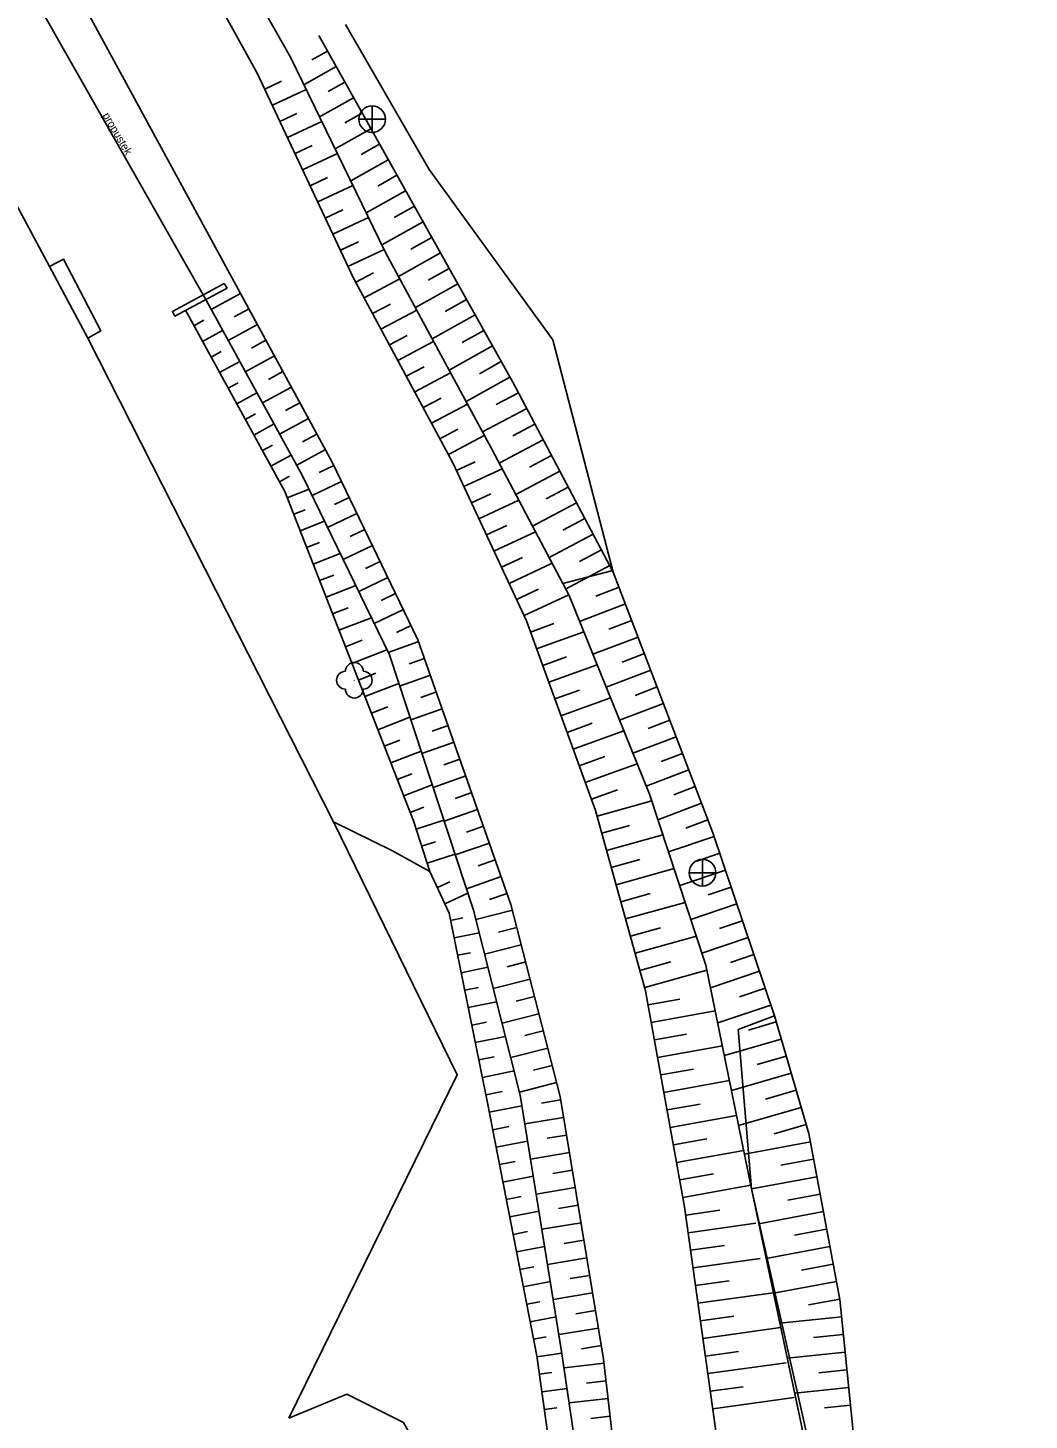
# Model space of a CAD drawing. Extents: x -747135 to -746147, y -1093269 to -1091735.
# Drawn here: x -746689.1 to -746632.7, y -1092579.8 to -1092501.6 of the extents above; entities that cross this region are included whole.
import ezdxf

# ---------------------------------------------------------------- set-up
doc = ezdxf.new("R2010")
doc.units = 0
for name, color, linetype in [('101', 7, 'Continuous'), ('1016', 7, 'Continuous'), ('105', 7, 'Continuous'), ('23700', 7, 'Continuous'), ('308', 7, 'Continuous'), ('316', 7, 'Continuous'), ('424', 7, 'Continuous'), ('803', 7, 'Continuous')]:
    doc.layers.add(name, color=color, linetype=linetype)

msp = doc.modelspace()

# ---------------------------------------------------------------- linework, layer by layer
at = {"layer": '101'}
for points in [[(-746672.69, -1092502.01), (-746661.78, -1092521.49), (-746656.13, -1092532.17)], [(-746674.28, -1092503.22), (-746668.93, -1092514.2), (-746662.98, -1092525.23), (-746658.61, -1092533.49), (-746654.09, -1092544.66), (-746650.92, -1092554.26), (-746648.35, -1092566.85), (-746644.79, -1092583.69), (-746644.13, -1092588.78), (-746644.17, -1092602.45), (-746642.4, -1092621.5)], [(-746672.201, -1092502.882), (-746673.082, -1092503.376)], [(-746671.713, -1092503.755), (-746673.525, -1092504.77)], [(-746675.725, -1092505.025), (-746674.779, -1092504.581)], [(-746671.224, -1092504.627), (-746672.155, -1092505.149)], [(-746675.3, -1092505.93), (-746673.395, -1092505.036)], [(-746670.735, -1092505.5), (-746672.647, -1092506.571)], [(-746674.875, -1092506.835), (-746673.916, -1092506.385)], [(-746670.247, -1092506.372), (-746671.228, -1092506.922)], [(-746674.45, -1092507.741), (-746672.519, -1092506.834)], [(-746669.758, -1092507.245), (-746671.77, -1092508.372)], [(-746674.025, -1092508.646), (-746673.053, -1092508.189)], [(-746673.6, -1092509.551), (-746671.643, -1092508.632)], [(-746669.269, -1092508.117), (-746670.3, -1092508.695)], [(-746668.781, -1092508.99), (-746670.892, -1092510.172)], [(-746673.174, -1092510.456), (-746672.19, -1092509.994)], [(-746668.292, -1092509.862), (-746669.373, -1092510.468)], [(-746672.749, -1092511.361), (-746670.767, -1092510.43)], [(-746667.804, -1092510.735), (-746670.015, -1092511.973)], [(-746672.324, -1092512.266), (-746671.327, -1092511.798)], [(-746667.315, -1092511.607), (-746668.446, -1092512.241)], [(-746671.899, -1092513.172), (-746669.891, -1092512.228)], [(-746666.826, -1092512.48), (-746669.137, -1092513.774)], [(-746666.338, -1092513.352), (-746667.509, -1092514.008)], [(-746671.474, -1092514.077), (-746670.463, -1092513.602)], [(-746671.049, -1092514.982), (-746669.015, -1092514.026)], [(-746665.849, -1092514.225), (-746668.205, -1092515.544)], [(-746665.36, -1092515.097), (-746666.545, -1092515.761)], [(-746670.611, -1092515.88), (-746669.608, -1092515.341)], [(-746670.137, -1092516.761), (-746668.131, -1092515.682)], [(-746677.089, -1092516.501), (-746678.748, -1092517.402)], [(-746664.872, -1092515.97), (-746667.255, -1092517.305)], [(-746643.03, -1092728.31), (-746645.35, -1092706.55), (-746647.64, -1092685.53), (-746650.22, -1092662.21), (-746652.01, -1092645.97), (-746654.41, -1092623.21), (-746657.16, -1092600.72), (-746657.52, -1092586.28), (-746659.03, -1092575.98), (-746661.36, -1092561.58), (-746663.99, -1092551.17), (-746668.72, -1092536.82), (-746673.6, -1092526.76), (-746679.03, -1092516.89)], [(-746676.612, -1092517.38), (-746677.439, -1092517.829)], [(-746669.663, -1092517.642), (-746668.66, -1092517.102)], [(-746669.19, -1092518.522), (-746667.181, -1092517.442)], [(-746664.383, -1092516.842), (-746665.582, -1092517.514)], [(-746680.19, -1092517.45), (-746674.6, -1092527.64), (-746667.37, -1092546.15), (-746666.44, -1092549)], [(-746679.709, -1092518.327), (-746679.145, -1092518.017)], [(-746663.894, -1092517.715), (-746666.306, -1092519.065)], [(-746679.228, -1092519.203), (-746678.098, -1092518.584)], [(-746676.135, -1092518.259), (-746677.784, -1092519.154)], [(-746668.716, -1092519.403), (-746667.711, -1092518.863)], [(-746663.406, -1092518.587), (-746664.618, -1092519.266)], [(-746678.747, -1092520.08), (-746678.182, -1092519.77)], [(-746675.658, -1092519.137), (-746676.48, -1092519.584)], [(-746668.242, -1092520.284), (-746666.232, -1092519.202)], [(-746662.917, -1092519.46), (-746665.356, -1092520.826)], [(-746678.266, -1092520.957), (-746677.134, -1092520.336)], [(-746675.18, -1092520.016), (-746676.82, -1092520.907)], [(-746662.428, -1092520.332), (-746663.655, -1092521.019)], [(-746674.703, -1092520.895), (-746675.521, -1092521.339)], [(-746667.769, -1092521.164), (-746666.763, -1092520.623)], [(-746667.295, -1092522.045), (-746665.282, -1092520.963)], [(-746661.94, -1092521.205), (-746664.406, -1092522.586)], [(-746677.785, -1092521.834), (-746677.219, -1092521.523)], [(-746677.304, -1092522.71), (-746676.17, -1092522.088)], [(-746674.226, -1092521.774), (-746675.856, -1092522.659)], [(-746661.465, -1092522.085), (-746662.714, -1092522.746)], [(-746673.748, -1092522.652), (-746674.561, -1092523.094)], [(-746666.821, -1092522.926), (-746665.814, -1092522.384)], [(-746666.347, -1092523.807), (-746664.332, -1092522.723)], [(-746676.823, -1092523.587), (-746676.256, -1092523.276)], [(-746673.271, -1092523.531), (-746674.892, -1092524.411)], [(-746660.998, -1092522.969), (-746663.489, -1092524.287)], [(-746676.342, -1092524.464), (-746675.206, -1092523.841)], [(-746672.794, -1092524.41), (-746673.602, -1092524.849)], [(-746665.874, -1092524.687), (-746664.866, -1092524.145)], [(-746665.4, -1092525.568), (-746663.383, -1092524.483)], [(-746660.53, -1092523.853), (-746661.772, -1092524.51)], [(-746675.861, -1092525.341), (-746675.293, -1092525.029)], [(-746660.062, -1092524.737), (-746662.546, -1092526.05)], [(-746675.38, -1092526.217), (-746674.242, -1092525.593)], [(-746672.316, -1092525.288), (-746673.928, -1092526.164)], [(-746664.948, -1092526.46), (-746663.898, -1092525.97)], [(-746659.595, -1092525.621), (-746660.837, -1092526.277)], [(-746674.899, -1092527.094), (-746674.33, -1092526.782)], [(-746671.847, -1092526.171), (-746672.673, -1092526.57)], [(-746664.526, -1092527.366), (-746662.379, -1092526.366)], [(-746659.127, -1092526.504), (-746661.611, -1092527.818)], [(-746674.463, -1092527.992), (-746673.235, -1092527.512)], [(-746671.412, -1092527.072), (-746673.062, -1092527.869)], [(-746658.66, -1092527.388), (-746659.901, -1092528.045)], [(-746670.977, -1092527.972), (-746671.801, -1092528.37)], [(-746664.104, -1092528.272), (-746663.007, -1092527.762)], [(-746663.681, -1092529.179), (-746661.443, -1092528.136)], [(-746658.192, -1092528.272), (-746660.675, -1092529.586)], [(-746674.099, -1092528.923), (-746673.448, -1092528.669)], [(-746670.541, -1092528.872), (-746672.189, -1092529.669)], [(-746657.724, -1092529.156), (-746658.966, -1092529.813)], [(-746673.735, -1092529.854), (-746672.36, -1092529.317)], [(-746670.106, -1092529.773), (-746670.929, -1092530.171)], [(-746663.259, -1092530.085), (-746662.117, -1092529.553)], [(-746662.836, -1092530.992), (-746660.506, -1092529.906)], [(-746673.371, -1092530.786), (-746672.646, -1092530.503)], [(-746669.671, -1092530.673), (-746671.316, -1092531.468)], [(-746657.257, -1092530.04), (-746659.74, -1092531.354)], [(-746673.007, -1092531.717), (-746671.484, -1092531.122)], [(-746662.414, -1092531.898), (-746661.226, -1092531.344)], [(-746656.789, -1092530.924), (-746658.031, -1092531.581)], [(-746669.236, -1092531.573), (-746670.058, -1092531.971)], [(-746661.991, -1092532.804), (-746659.57, -1092531.676)], [(-746656.153, -1092532.083), (-746658.966, -1092532.816)], [(-746656.321, -1092531.808), (-746658.805, -1092533.122)], [(-746672.644, -1092532.649), (-746671.845, -1092532.337)], [(-746672.28, -1092533.58), (-746670.608, -1092532.927)], [(-746668.8, -1092532.473), (-746670.443, -1092533.268)], [(-746655.805, -1092533.02), (-746657.102, -1092533.517)], [(-746668.365, -1092533.374), (-746669.186, -1092533.771)], [(-746661.569, -1092533.711), (-746660.335, -1092533.136)], [(-746661.146, -1092534.617), (-746658.633, -1092533.446)], [(-746671.916, -1092534.512), (-746671.043, -1092534.171)], [(-746667.93, -1092534.274), (-746669.57, -1092535.067)], [(-746655.447, -1092533.954), (-746658.023, -1092534.94)], [(-746671.552, -1092535.443), (-746669.733, -1092534.733)], [(-746667.495, -1092535.174), (-746668.314, -1092535.571)], [(-746660.778, -1092535.546), (-746659.471, -1092535.07)], [(-746655.09, -1092534.888), (-746656.369, -1092535.378)], [(-746671.188, -1092536.375), (-746670.241, -1092536.005)], [(-746667.071, -1092536.08), (-746668.787, -1092536.682)], [(-746660.436, -1092536.486), (-746657.788, -1092535.522)], [(-746654.732, -1092535.822), (-746657.273, -1092536.794)], [(-746670.824, -1092537.306), (-746668.857, -1092536.538)], [(-746660.094, -1092537.426), (-746658.753, -1092536.937)], [(-746654.375, -1092536.756), (-746655.636, -1092537.239)], [(-746666.74, -1092537.023), (-746667.597, -1092537.324)], [(-746659.752, -1092538.365), (-746657.037, -1092537.377)], [(-746654.018, -1092537.69), (-746656.523, -1092538.649)], [(-746670.461, -1092538.238), (-746669.483, -1092537.856)], [(-746670.097, -1092539.169), (-746668.191, -1092538.425)], [(-746666.409, -1092537.967), (-746668.141, -1092538.575)], [(-746666.077, -1092538.91), (-746666.953, -1092539.218)], [(-746659.41, -1092539.305), (-746658.036, -1092538.805)], [(-746659.068, -1092540.245), (-746656.286, -1092539.232)], [(-746653.66, -1092538.624), (-746654.904, -1092539.1)], [(-746669.733, -1092540.101), (-746668.805, -1092539.738)], [(-746665.746, -1092539.854), (-746667.515, -1092540.475)], [(-746653.303, -1092539.558), (-746655.772, -1092540.503)], [(-746669.369, -1092541.032), (-746667.564, -1092540.327)], [(-746665.414, -1092540.797), (-746666.308, -1092541.111)], [(-746658.726, -1092541.184), (-746657.319, -1092540.672)], [(-746652.945, -1092540.492), (-746654.171, -1092540.961)], [(-746669.005, -1092541.964), (-746668.128, -1092541.621)], [(-746658.384, -1092542.124), (-746655.536, -1092541.087)], [(-746652.588, -1092541.426), (-746655.022, -1092542.357)], [(-746668.641, -1092542.895), (-746666.937, -1092542.229)], [(-746665.083, -1092541.741), (-746666.889, -1092542.375)], [(-746652.231, -1092542.36), (-746653.439, -1092542.822)], [(-746664.752, -1092542.684), (-746665.664, -1092543.005)], [(-746658.042, -1092543.064), (-746656.601, -1092542.539)], [(-746657.7, -1092544.003), (-746654.785, -1092542.942)], [(-746668.278, -1092543.826), (-746667.451, -1092543.503)], [(-746664.42, -1092543.628), (-746666.263, -1092544.275)], [(-746651.873, -1092543.294), (-746654.271, -1092544.211)], [(-746667.914, -1092544.758), (-746666.31, -1092544.132)], [(-746664.089, -1092544.571), (-746665.019, -1092544.898)], [(-746657.358, -1092544.943), (-746655.884, -1092544.406)], [(-746651.516, -1092544.228), (-746652.722, -1092544.689)], [(-746667.55, -1092545.689), (-746666.773, -1092545.386)], [(-746663.758, -1092545.515), (-746665.637, -1092546.175)], [(-746657.041, -1092545.891), (-746653.966, -1092545.036)], [(-746651.158, -1092545.162), (-746653.614, -1092546.101)], [(-746667.213, -1092546.631), (-746665.654, -1092546.122)], [(-746650.801, -1092546.096), (-746652.051, -1092546.574)], [(-746663.426, -1092546.458), (-746664.375, -1092546.791)], [(-746656.773, -1092546.854), (-746655.212, -1092546.42)], [(-746656.505, -1092547.818), (-746653.338, -1092546.937)], [(-746650.452, -1092547.033), (-746653.021, -1092547.896)], [(-746666.903, -1092547.581), (-746666.122, -1092547.326)], [(-746663.095, -1092547.402), (-746665.01, -1092548.074)], [(-746666.593, -1092548.532), (-746665.028, -1092548.021)], [(-746662.763, -1092548.345), (-746663.73, -1092548.685)], [(-746656.237, -1092548.781), (-746654.631, -1092548.334)], [(-746650.133, -1092547.98), (-746651.42, -1092548.413)], [(-746662.432, -1092549.289), (-746664.384, -1092549.974)], [(-746655.969, -1092549.744), (-746652.71, -1092548.838)], [(-746649.814, -1092548.928), (-746652.394, -1092549.796)], [(-746666.021, -1092549.908), (-746665.32, -1092549.584)], [(-746665.602, -1092550.816), (-746664.304, -1092550.217)], [(-746662.101, -1092550.232), (-746663.086, -1092550.578)], [(-746655.701, -1092550.708), (-746654.049, -1092550.248)], [(-746649.496, -1092549.876), (-746650.788, -1092550.311)], [(-746655.433, -1092551.671), (-746652.083, -1092550.739)], [(-746649.177, -1092550.824), (-746651.767, -1092551.695)], [(-746665.276, -1092551.754), (-746664.594, -1092551.616)], [(-746661.797, -1092551.184), (-746663.854, -1092551.71)], [(-746648.858, -1092551.772), (-746650.156, -1092552.208)], [(-746665.078, -1092552.735), (-746663.667, -1092552.449)], [(-746661.549, -1092552.153), (-746662.579, -1092552.416)], [(-746655.165, -1092552.635), (-746653.467, -1092552.162)], [(-746654.897, -1092553.598), (-746651.455, -1092552.641)], [(-746661.301, -1092553.122), (-746663.364, -1092553.649)], [(-746648.54, -1092552.72), (-746651.14, -1092553.594)], [(-746664.879, -1092553.715), (-746664.15, -1092553.567)], [(-746661.054, -1092554.09), (-746662.086, -1092554.355)], [(-746654.629, -1092554.562), (-746652.885, -1092554.076)], [(-746648.221, -1092553.667), (-746649.54, -1092554.111)], [(-746664.681, -1092554.695), (-746663.176, -1092554.39)], [(-746654.361, -1092555.525), (-746650.861, -1092554.551)], [(-746647.902, -1092554.615), (-746650.658, -1092555.542)], [(-746664.482, -1092555.675), (-746663.707, -1092555.518)], [(-746660.806, -1092555.059), (-746662.874, -1092555.588)], [(-746647.583, -1092555.563), (-746649.02, -1092556.046)], [(-746664.284, -1092556.655), (-746662.686, -1092556.331)], [(-746660.558, -1092556.028), (-746661.593, -1092556.293)], [(-746654.167, -1092556.505), (-746652.38, -1092556.183)], [(-746647.265, -1092556.511), (-746650.255, -1092557.517)], [(-746660.31, -1092556.997), (-746662.384, -1092557.527)], [(-746653.989, -1092557.489), (-746650.393, -1092556.841)], [(-746664.086, -1092557.635), (-746663.263, -1092557.469)], [(-746660.062, -1092557.966), (-746661.101, -1092558.231)], [(-746653.812, -1092558.473), (-746652.002, -1092558.147)], [(-746646.96, -1092557.463), (-746648.52, -1092557.918)], [(-746663.887, -1092558.615), (-746662.196, -1092558.273)], [(-746653.634, -1092559.457), (-746649.993, -1092558.801)], [(-746646.68, -1092558.423), (-746649.88, -1092559.356)], [(-746663.689, -1092559.595), (-746662.82, -1092559.419)], [(-746659.815, -1092558.935), (-746661.894, -1092559.466)], [(-746646.4, -1092559.383), (-746648.04, -1092559.861)], [(-746663.49, -1092560.575), (-746661.705, -1092560.214)], [(-746659.567, -1092559.903), (-746660.608, -1092560.17)], [(-746653.456, -1092560.442), (-746651.625, -1092560.111)], [(-746646.12, -1092560.343), (-746649.478, -1092561.322)], [(-746659.319, -1092560.872), (-746661.404, -1092561.406)], [(-746653.279, -1092561.426), (-746649.593, -1092560.761)], [(-746663.292, -1092561.556), (-746662.376, -1092561.37)], [(-746659.088, -1092561.844), (-746660.173, -1092562.025)], [(-746645.84, -1092561.303), (-746647.559, -1092561.804)], [(-746663.098, -1092562.536), (-746661.263, -1092562.179)], [(-746658.924, -1092562.831), (-746661.099, -1092563.192)], [(-746653.101, -1092562.41), (-746651.247, -1092562.075)], [(-746652.924, -1092563.394), (-746649.193, -1092562.721)], [(-746645.56, -1092562.263), (-746649.077, -1092563.289)], [(-746662.906, -1092563.518), (-746662.005, -1092563.343)], [(-746645.281, -1092563.223), (-746647.078, -1092563.748)], [(-746662.715, -1092564.5), (-746660.943, -1092564.155)], [(-746658.76, -1092563.817), (-746659.85, -1092563.998)], [(-746652.746, -1092564.378), (-746650.87, -1092564.04)], [(-746645.045, -1092564.194), (-746648.751, -1092564.885)], [(-746658.597, -1092564.804), (-746660.78, -1092565.166)], [(-746652.569, -1092565.362), (-746648.793, -1092564.681)], [(-746644.862, -1092565.177), (-746646.707, -1092565.521)], [(-746662.524, -1092565.481), (-746661.654, -1092565.312)], [(-746658.433, -1092565.791), (-746659.527, -1092565.972)], [(-746662.333, -1092566.463), (-746660.624, -1092566.13)], [(-746652.391, -1092566.346), (-746650.492, -1092566.004)], [(-746652.214, -1092567.33), (-746648.393, -1092566.641)], [(-746644.679, -1092566.16), (-746648.351, -1092566.845)], [(-746662.142, -1092567.444), (-746661.303, -1092567.281)], [(-746658.27, -1092566.777), (-746660.46, -1092567.14)], [(-746644.495, -1092567.143), (-746646.32, -1092567.483)], [(-746661.951, -1092568.426), (-746660.304, -1092568.105)], [(-746658.106, -1092567.764), (-746659.203, -1092567.946)], [(-746652.055, -1092568.317), (-746650.144, -1092568.051)], [(-746644.312, -1092568.126), (-746647.937, -1092568.802)], [(-746657.942, -1092568.75), (-746660.141, -1092569.115)], [(-746651.917, -1092569.308), (-746648.109, -1092568.776)], [(-746661.76, -1092569.408), (-746660.952, -1092569.25)], [(-746657.779, -1092569.737), (-746658.88, -1092569.919)], [(-746644.129, -1092569.109), (-746645.93, -1092569.445)], [(-746661.569, -1092570.389), (-746659.985, -1092570.081)], [(-746651.778, -1092570.298), (-746649.881, -1092570.034)], [(-746643.945, -1092570.092), (-746647.523, -1092570.76)], [(-746661.378, -1092571.371), (-746660.601, -1092571.219)], [(-746657.615, -1092570.723), (-746659.821, -1092571.089)], [(-746651.64, -1092571.289), (-746647.86, -1092570.761)], [(-746643.762, -1092571.075), (-746645.539, -1092571.407)], [(-746661.187, -1092572.352), (-746659.665, -1092572.056)], [(-746657.451, -1092571.71), (-746658.556, -1092571.893)], [(-746651.502, -1092572.279), (-746649.619, -1092572.016)], [(-746643.579, -1092572.058), (-746647.11, -1092572.717)], [(-746657.288, -1092572.696), (-746659.502, -1092573.063)], [(-746651.364, -1092573.27), (-746647.144, -1092572.681)], [(-746660.996, -1092573.334), (-746660.25, -1092573.189)], [(-746657.124, -1092573.683), (-746658.233, -1092573.867)], [(-746643.395, -1092573.042), (-746645.149, -1092573.369)], [(-746660.805, -1092574.315), (-746659.345, -1092574.031)], [(-746651.225, -1092574.26), (-746649.356, -1092573.999)], [(-746643.292, -1092574.036), (-746646.757, -1092574.386)], [(-746660.614, -1092575.297), (-746659.9, -1092575.158)], [(-746656.96, -1092574.669), (-746659.182, -1092575.038)], [(-746651.087, -1092575.25), (-746646.716, -1092574.64)], [(-746643.192, -1092575.031), (-746644.87, -1092575.201)], [(-746660.425, -1092576.279), (-746659.015, -1092576.081)], [(-746656.797, -1092575.656), (-746657.91, -1092575.84)], [(-746650.949, -1092576.241), (-746649.094, -1092575.982)], [(-746643.091, -1092576.026), (-746646.341, -1092576.354)], [(-746656.645, -1092576.644), (-746658.895, -1092576.9)], [(-746650.811, -1092577.231), (-746646.401, -1092576.616)], [(-746660.286, -1092577.269), (-746659.578, -1092577.17)], [(-746656.531, -1092577.637), (-746657.641, -1092577.764)], [(-746642.991, -1092577.021), (-746644.562, -1092577.18)], [(-746660.147, -1092578.26), (-746658.725, -1092578.06)], [(-746650.673, -1092578.222), (-746648.831, -1092577.965)], [(-746642.89, -1092578.016), (-746645.925, -1092578.323)], [(-746660.008, -1092579.25), (-746659.294, -1092579.15)], [(-746656.418, -1092578.631), (-746658.605, -1092578.88)], [(-746650.534, -1092579.212), (-746645.951, -1092578.572)], [(-746642.79, -1092579.011), (-746644.253, -1092579.159)], [(-746656.305, -1092579.625), (-746657.382, -1092579.747)]]:
    msp.add_lwpolyline(points, dxfattribs=at)
at = {"layer": '1016'}
for points in [[(-746680.08, -1092497.02), (-746676.15, -1092504.12)], [(-746677.329, -1092516.059), (-746686.53, -1092499.12)], [(-746676.15, -1092504.12), (-746670.74, -1092515.64), (-746665.13, -1092526.07), (-746661.01, -1092534.91), (-746657.13, -1092545.57), (-746654.31, -1092555.71), (-746652.12, -1092567.85), (-746649.95, -1092583.4), (-746648.25, -1092600.5), (-746646.08, -1092622.58)], [(-746677.85, -1092516.21), (-746680.78, -1092517.78), (-746680.922, -1092517.516), (-746678.018, -1092515.949), (-746677.85, -1092516.21)], [(-746640.293, -1092727.76), (-746642.73, -1092706.84), (-746645.07, -1092684.23), (-746647.45, -1092662.17), (-746649.23, -1092645.87), (-746651.64, -1092623.4), (-746654, -1092600.5), (-746655.65, -1092585.38), (-746656.67, -1092576.42), (-746659.12, -1092561.65), (-746661.88, -1092550.86), (-746667.11, -1092535.97), (-746671.93, -1092526), (-746677.329, -1092516.06)]]:
    msp.add_lwpolyline(points, dxfattribs=at)
at = {"layer": '23700'}
for points in [[(-746678.42, -1092495.91), (-746674.28, -1092503.22)], [(-746688.39, -1092500.4), (-746679.03, -1092516.89)]]:
    msp.add_lwpolyline(points, dxfattribs=at)
at = {"layer": '308'}
msp.add_lwpolyline([(-746685.68, -1092519.02), (-746689.71, -1092511.48)], dxfattribs=at)
at = {"layer": '316'}
for p, q in [((-746669.691, -1092507.458), (-746669.69, -1092505.963)), ((-746668.938, -1092506.716), (-746670.438, -1092506.711)), ((-746651.111, -1092549.818), (-746651.11, -1092548.323)), ((-746650.358, -1092549.076), (-746651.858, -1092549.071))]:
    msp.add_line(p, q, dxfattribs=at)
for centre in [(-746669.69, -1092506.71), (-746651.11, -1092549.07)]:
    msp.add_circle(centre, 0.75, dxfattribs=at)
at = {"layer": '424'}
for points in [[(-746632.74, -1092626.58), (-746635.64, -1092620.77), (-746637.67, -1092615.33), (-746638.38, -1092607.28), (-746642.34, -1092583.46), (-746643.39, -1092573.07), (-746645.13, -1092563.74), (-746647.06, -1092557.12), (-746650.52, -1092546.83), (-746656.13, -1092532.17), (-746659.53, -1092519.12), (-746666.48, -1092509.53), (-746671.18, -1092501.38)], [(-746671.86, -1092546.22), (-746668.58, -1092547.82), (-746666.44, -1092549)], [(-746666.44, -1092549), (-746665.36, -1092551.34), (-746663.2, -1092562.01), (-746660.43, -1092576.24), (-746658.93, -1092586.95), (-746657.16, -1092600.72), (-746656.07, -1092616.52), (-746651.4, -1092662.02)], [(-746647.06, -1092557.12), (-746649.1, -1092557.89), (-746648.35, -1092566.85), (-746644.58, -1092583.56), (-746643.94, -1092588.6), (-746643.94, -1092602.65), (-746640.7, -1092621.81)], [(-746674.37, -1092579.73), (-746671.11, -1092578.39), (-746667.92, -1092579.98), (-746662.95, -1092588.94), (-746660.74, -1092596.69), (-746659.38, -1092604.06), (-746657.87, -1092616.28)]]:
    msp.add_lwpolyline(points, dxfattribs=at)
msp.add_circle((-746670.69, -1092538.25), 0.0005, dxfattribs=at)
for centre, start, end in [((-746671.19, -1092538.25), 89.99999, 269.99999), ((-746670.69, -1092537.75), 0, 179.99999), ((-746670.19, -1092538.25), 270, 89.99999), ((-746670.69, -1092538.75), 179.99999, 359.99999)]:
    msp.add_arc(centre, 0.5, start, end, dxfattribs=at)
at = {"layer": '803'}
for points in [[(-746685.68, -1092519.02), (-746684.95, -1092518.61), (-746687.04, -1092514.58), (-746687.83, -1092514.99)], [(-746674.37, -1092579.73), (-746664.9, -1092560.44), (-746671.86, -1092546.22), (-746685.68, -1092519.02)]]:
    msp.add_lwpolyline(points, dxfattribs=at)

# ---------------------------------------------------------------- texts
at = {"layer": '105'}
msp.add_text('propustek', height=0.45, rotation=300.26164, dxfattribs=at).set_placement((-746684.867, -1092506.493))

doc.saveas('drawing.dxf')
